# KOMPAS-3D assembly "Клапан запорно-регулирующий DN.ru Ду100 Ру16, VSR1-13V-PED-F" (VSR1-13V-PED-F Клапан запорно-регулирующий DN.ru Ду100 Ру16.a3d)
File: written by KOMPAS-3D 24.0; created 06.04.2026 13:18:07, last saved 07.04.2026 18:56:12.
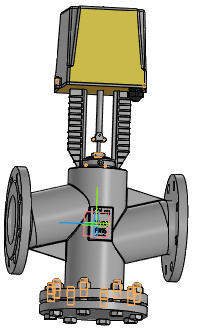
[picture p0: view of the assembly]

Document properties: Автор: R2D2; Полное имя файла: E:\Работа\Зайцев\Солянка\VSR1-13V-PED-F Клапан запорно-регулирующий DN.ru\DN100\исходные материалы\VSR1-13V-PED-F Клапан запорно-регулирующий DN.ru Ду100 Ру16.a3d

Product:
- Component [detail]: Фланец  | qty 2  | pos. 1  | Масса: 4.457556; Автор: R2D2; source file: Фланец.m3d
- Component [detail]: Фланец  | qty 1  | pos. 2  | Масса: 4.457556; Автор: R2D2; source file: Фланец.m3d
- Component [detail]: Корпус  | qty 1  | pos. 3  | Масса: 6.9; Автор: R2D2; source file: Корпус.m3d
- Component [detail]: Электропривод  | qty 1  | pos. 6  | Масса: 0.101125; Автор: R2D2; source file: Электропривод.m3d
- Component [standard]: Болт с шестигранной головкой ГОСТ Р ИСО 4014 - М16 x 65  | qty 8  | Материал: Не определено (density 1000 kg/m3); Масса: 0.1404; Раздел спецификации: Стандартные изделия; Рассекать на разрезах: no; additional columns: ГОСТ Р ИСО 4014-2013
- Component [standard]: Гайка М16-6H ГОСТ 5915-70  | qty 8  | Масса: 0.03761; Раздел спецификации: Стандартные изделия; Рассекать на разрезах: no; additional columns: М1,6-6H
- Part/product: Клапан запорно-регулирующий DN.ru Ду100 Ру16  | designation VSR1-13V-PED-F
    Масса: 33.7
    Раздел спецификации: Прочие изделия
    Примечание: D090-02894

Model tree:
1. Эскиз:1
2. Ось конической поверхности:19
3. Смещенная плоскость:19
4. ЛСК:19  (with: Плоскость XY, Плоскость ZX, Плоскость ZY, Ось X, Ось Y, Ось Z)
     Ось X. Y = -1; Ось Y. X = 1; Ось Z. Z = 1; Точка начала. Х = -34.4415; Точка начала. Y = -186; Точка начала. Z = -83.1492
5. Болтовое соединение
6. Массив по концентрической сетке:3  (with: Грань.Элемент выдавливания:1, Грань.Элемент вращения:1, Грань.Элемент выдавливания:8)  (8 pattern instances)
     Шаг 2 = 360; Ориентация = 2; Расстояние = -42

Expressions: VSR1-13V-PED-F; -L/2
Referenced files in E:\Работа\Зайцев\Солянка\VSR1-13V-PED-F Клапан запорно-регулирующий DN.ru\DN100\исходные материалы\: Фланец.m3d, Корпус.m3d, Электропривод.m3d
Referenced files in C:\Program Files\ASCON\KOMPAS-3D v24\Libs\PolynomLib\DATA\vault\Methods\Kompas\3D\: PLib_Bolt_1_ISO_1100.m3d, PLib_Nut_OST92_900.m3d
Referenced files in E:\Работа\Зайцев\Солянка\VSR1-13V-PED-F Клапан запорно-регулирующий DN.ru\DN20\исходные материалы\: Фланец.m3d
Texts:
  Болт с шестигранной головкой
  Крепежное изделие ГОСТ
  Программные изделия  и базы данных
  Edge1
  Edge2
  TKR3D
  Справочник стандартных изделий
  Фланец (1)
  Фланец (2)
  Фланец (3)
  Болт с шестигранной головкой ГОСТ Р ИСО 4014 - М16 x 65 (1)
  hole1
  hole2
  Гайка М16-6H ГОСТ 5915-70 (1)
  bcut1
  hcut1
  cut1
  Плоскость XY.Начало координат
  Ось Z.Начало координат
  Плоскость ZY.Начало координат
  Плоскость ZX.Начало координат
  Ось Y.Начало координат
  Plane. Начало координат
